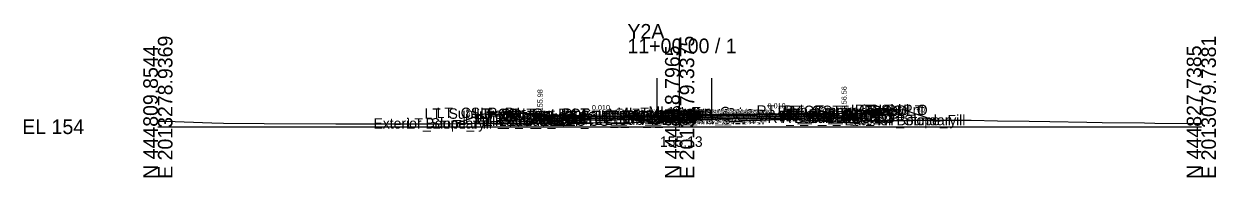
# Model space of a CAD drawing. Extents: x -26 to 203, y -10 to 5517.
# Drawn here: x -25.7 to 202.8, y 1990.3 to 2019.8 of the extents above; entities that cross this region are included whole.
import ezdxf

# ---------------------------------------------------------------- set-up
doc = ezdxf.new("R2010")
doc.units = 0
for name, color, linetype in [('Default', 7, 'Continuous'), ('Exist Cross Section Cell', 7, 'Continuous'), ('Exist XS Center Line Elevation Label', 7, 'Continuous'), ('Exist XS Ground Line', 7, 'Continuous'), ('Prop CMT Conc Surface', 7, 'Continuous'), ('Prop CMT Concrete Structures', 7, 'Continuous'), ('Prop CMT Pvmt Course 1', 7, 'Continuous'), ('Prop CMT Pvmt Course 1 CG', 7, 'Continuous'), ('Prop CMT Pvmt Course 2', 7, 'Continuous'), ('Prop CMT Pvmt Course 3', 7, 'Continuous'), ('Prop CMT Pvmt Surface', 7, 'Continuous'), ('Prop CMT Slope Grass', 7, 'Continuous'), ('Prop CMT Subgrade Earthwork', 7, 'Continuous'), ('Prop XS Earthwork Shape', 7, 'Continuous'), ('Prop XS Hydro Elevations', 7, 'Continuous'), ('Prop XS SE Text', 7, 'Continuous'), ('Prop XS Side Slope Text', 7, 'Continuous'), ('Scratch_Level_0', 7, 'Continuous'), ('Scratch_Level_3', 7, 'Continuous')]:
    doc.layers.add(name, color=color, linetype=linetype)

msp = doc.modelspace()

# ---------------------------------------------------------------- linework, layer by layer
at = {"layer": 'Exist Cross Section Cell'}
for p, q in [((100, 2000), (100, 2016.93)), ((0, 2000), (100, 2000)), ((100, 2000), (200, 2000))]:
    msp.add_line(p, q, dxfattribs=at)
at = {"layer": 'Exist XS Ground Line'}
msp.add_lwpolyline([(0, 2001.09), (1.54, 2001.04), (10.32, 2000.73), (12.58, 2000.71), (20.36, 2000.6), (34.09, 2000.57), (38.11, 2000.57), (39.58, 2000.57), (43.69, 2000.55), (50.48, 2000.59), (54.5, 2000.59), (60.52, 2000.71), (67.74, 2000.66), (70.57, 2000.66), (78.77, 2000.81), (81.06, 2000.81), (90.15, 2000.74), (91.36, 2000.8), (96.96, 2001), (100, 2001.13), (107.18, 2001.43), (109.11, 2001.5), (109.53, 2001), (111.15, 2001.1), (111.78, 2001.12), (121.22, 2001.44), (122.3, 2001.37), (132.6, 2000.73), (134.22, 2000.63), (134.65, 2001.13), (135.26, 2001.12), (139.78, 2001.11), (140.39, 2001.11), (147.97, 2001.28), (155.86, 2001.25), (160.94, 2001.16), (167.02, 2001.05), (170.98, 2001.01), (178.05, 2000.87), (181.02, 2000.8), (189.09, 2000.74), (191.06, 2000.7), (200, 2000.61)], dxfattribs=at)
at = {"layer": 'Prop CMT Conc Surface'}
for points in [[(73.26, 2001.98), (73.26, 2002.48), (72.76, 2002.48)], [(75.26, 2002.08), (73.26, 2001.98)], [(129.54, 2002.62), (131.54, 2002.56)], [(131.54, 2002.56), (131.54, 2003.06), (132.04, 2003.06)]]:
    msp.add_lwpolyline(points, dxfattribs=at)
at = {"layer": 'Prop CMT Concrete Structures'}
for p, q in [((95.69, 2002.45), (95.68, 2002.29)), ((96.44, 2002.7), (95.69, 2002.45)), ((100.98, 2002.9), (96.44, 2002.7)), ((105.41, 2002.81), (100.98, 2002.9)), ((106.16, 2002.56), (105.41, 2002.81)), ((106.17, 2002.39), (106.16, 2002.56))]:
    msp.add_line(p, q, dxfattribs=at)
for points in [[(75.26, 2002.08), (73.26, 2001.98), (73.26, 2002.48), (72.76, 2002.48)], [(72.76, 2002.48), (72.76, 2001.47), (75.26, 2001.5)], [(75.26, 2001.5), (75.26, 2002.08)], [(94.41, 2002.27), (107.45, 2002.4)], [(129.54, 2002.62), (131.54, 2002.56), (131.54, 2003.06), (132.04, 2003.06)], [(132.04, 2003.06), (132.04, 2002.07), (129.54, 2002.04)], [(129.54, 2002.04), (129.54, 2002.62)], [(142.33, 2003.28), (136.65, 2003.17)], [(136.65, 2003.17), (136.65, 2002.83)], [(136.65, 2002.83), (142.33, 2002.95)], [(142.33, 2002.95), (142.33, 2003.28)]]:
    msp.add_lwpolyline(points, dxfattribs=at)
at = {"layer": 'Prop CMT Pvmt Course 1'}
for points in [[(94.41, 2002.27), (75.26, 2002.08)], [(75.26, 2002.08), (75.26, 2001.83)], [(75.26, 2001.83), (94.41, 2002.02)], [(94.41, 2002.27), (107.45, 2002.4)], [(107.45, 2002.15), (94.41, 2002.02)], [(95.68, 2002.04), (95.68, 2002.29)], [(95.68, 2002.04), (95.68, 2002.29)], [(106.17, 2002.14), (106.17, 2002.39)], [(106.17, 2002.39), (106.17, 2002.14)], [(107.45, 2002.4), (129.54, 2002.62)], [(129.54, 2002.37), (107.45, 2002.15)], [(129.54, 2002.62), (129.54, 2002.37)]]:
    msp.add_lwpolyline(points, dxfattribs=at)
for points in [[(95.68, 2002.04), (95.68, 2002.16), (95.68, 2002.16), (95.68, 2002.04)], [(106.17, 2002.14), (106.17, 2002.27), (106.17, 2002.27), (106.17, 2002.14)]]:
    msp.add_lwpolyline(points, close=True, dxfattribs=at)
at = {"layer": 'Prop CMT Pvmt Course 1 CG'}
for points in [[(129.54, 2002.04), (132.54, 2002.07), (132.87, 2001.74)], [(129.54, 2001.71), (129.54, 2002.04)], [(75.26, 2001.5), (72.26, 2001.47), (71.93, 2001.13)], [(71.93, 2001.13), (75.26, 2001.17)], [(75.26, 2001.17), (75.26, 2001.5)], [(132.87, 2001.74), (129.54, 2001.71)]]:
    msp.add_lwpolyline(points, dxfattribs=at)
at = {"layer": 'Prop CMT Pvmt Course 2'}
for points in [[(94.41, 2002.02), (75.26, 2001.83)], [(94.41, 2002.02), (107.45, 2002.15)], [(95.68, 2001.7), (95.68, 2002.04)], [(95.68, 2001.7), (95.68, 2002.04)], [(106.17, 2001.81), (106.17, 2002.14)], [(106.17, 2002.14), (106.17, 2001.81)], [(107.45, 2002.15), (129.54, 2002.37)], [(129.54, 2002.04), (107.45, 2001.82)], [(129.54, 2002.37), (129.54, 2002.04)], [(75.26, 2001.83), (75.26, 2001.5)], [(75.26, 2001.5), (94.41, 2001.69)], [(107.45, 2001.82), (94.41, 2001.69)]]:
    msp.add_lwpolyline(points, dxfattribs=at)
at = {"layer": 'Prop CMT Pvmt Course 3'}
for points in [[(107.45, 2001.82), (129.54, 2002.04)], [(129.54, 2002.04), (129.54, 2001.71)], [(94.41, 2001.69), (75.26, 2001.5)], [(75.26, 2001.5), (75.26, 2001.17)], [(75.26, 2001.17), (94.41, 2001.36)], [(94.41, 2001.69), (107.45, 2001.82)], [(107.45, 2001.49), (94.41, 2001.36)], [(95.68, 2001.37), (95.68, 2001.7)], [(95.68, 2001.37), (95.68, 2001.7)], [(106.17, 2001.47), (106.17, 2001.81)], [(106.17, 2001.81), (106.17, 2001.47)], [(129.54, 2001.71), (107.45, 2001.49)]]:
    msp.add_lwpolyline(points, dxfattribs=at)
at = {"layer": 'Prop CMT Pvmt Surface'}
for points in [[(94.41, 2002.27), (75.26, 2002.08)], [(94.41, 2002.27), (107.45, 2002.4)], [(107.45, 2002.4), (129.54, 2002.62)]]:
    msp.add_lwpolyline(points, dxfattribs=at)
at = {"layer": 'Prop CMT Slope Grass'}
for points in [[(72.76, 2002.48), (63.26, 2002.67), (57.18, 2000.64)], [(132.04, 2003.06), (142.33, 2003.27)], [(142.33, 2003.27), (142.83, 2003.28), (148.85, 2001.27)]]:
    msp.add_lwpolyline(points, dxfattribs=at)
at = {"layer": 'Prop CMT Subgrade Earthwork'}
for points in [[(75.26, 2001.17), (71.93, 2001.13), (70.53, 2002.53)], [(75.26, 2001.17), (71.93, 2001.13), (70.53, 2002.53)], [(129.54, 2001.71), (132.87, 2001.74), (134.23, 2003.11)], [(129.54, 2001.71), (132.87, 2001.74), (134.23, 2003.11)], [(94.41, 2001.36), (75.26, 2001.17)], [(94.41, 2001.36), (107.45, 2001.49)], [(107.45, 2001.49), (129.54, 2001.71)]]:
    msp.add_lwpolyline(points, dxfattribs=at)
at = {"layer": 'Prop XS Earthwork Shape'}
for points in [[(70.53, 2002.53), (63.26, 2002.67), (57.18, 2000.64), (60.52, 2000.71), (67.74, 2000.66), (70.57, 2000.66), (78.77, 2000.81), (81.06, 2000.81), (90.15, 2000.74), (91.36, 2000.8), (96.96, 2001), (100, 2001.13), (107.18, 2001.43), (109.1, 2001.5), (107.45, 2001.49), (94.41, 2001.36), (75.26, 2001.17), (71.93, 2001.13)], [(142.83, 2003.28), (148.85, 2001.27), (147.97, 2001.28), (140.39, 2001.11), (139.78, 2001.11), (135.26, 2001.12), (134.65, 2001.13), (134.22, 2000.63), (132.6, 2000.73), (122.3, 2001.37), (121.22, 2001.44), (111.78, 2001.12), (111.15, 2001.1), (109.53, 2001), (109.11, 2001.5), (129.54, 2001.71), (132.87, 2001.74), (134.23, 2003.11), (136.65, 2003.17), (136.65, 2002.83), (142.33, 2002.95), (142.33, 2003.27)]]:
    msp.add_lwpolyline(points, close=True, dxfattribs=at)
at = {"layer": 'Scratch_Level_3'}
for p, q in [((95.68, 2002.29), (95.68, 2009.3)), ((106.17, 2002.39), (106.17, 2009.3))]:
    msp.add_line(p, q, dxfattribs=at)

# ---------------------------------------------------------------- texts
at = {"layer": 'Default'}
msp.add_text('-', height=0.0001, dxfattribs=at).set_placement((0, 2000))
at = {"layer": 'Exist Cross Section Cell'}
for s, p in [('Y2A', (90, 2016.93)), ('11+00.00 / 1', (90, 2014.13)), ('EL 154', (-26, 1998.6))]:
    msp.add_text(s, height=2.8, dxfattribs=at).set_placement(p)
for s, p in [('E 2013278.9369', (2.8, 1990)), ('E 2013179.3375', (102.8, 1990)), ('E 2013079.7381', (202.8, 1990)), ('N 444809.8544', (0, 1990)), ('N 444818.7965', (100, 1990)), ('N 444827.7385', (200, 1990))]:
    msp.add_text(s, height=2.8, rotation=90, dxfattribs=at).set_placement(p)
at = {"layer": 'Exist XS Center Line Elevation Label'}
msp.add_text('155.13', height=2, dxfattribs=at).set_placement((96.23, 1996.13))
at = {"layer": 'Prop XS Hydro Elevations'}
for s, p in [('155.98', (73.76, 2002.98)), ('156.56', (132.04, 2003.56))]:
    msp.add_text(s, height=1, rotation=90, dxfattribs=at).set_placement(p)
at = {"layer": 'Prop XS SE Text'}
for p in [(116.86, 2003.5), (83.2, 2003.16)]:
    msp.add_text('0.010', height=1, rotation=0.5729, dxfattribs=at).set_placement(p)
at = {"layer": 'Prop XS Side Slope Text'}
for rotation, p in [(18.4349, (59.23, 2002.12)), (341.5668, (145.3, 2003.25))]:
    msp.add_text('3:1', height=1, rotation=rotation, dxfattribs=at).set_placement(p)
at = {"layer": 'Scratch_Level_0'}
for s, p in [('RT_Shld_O', (133.57, 2002.24)), ('CSLP_Pnt', (134.4, 2002.25)), ('LT_Sub_Trench_Out_DLT', (51.1, 2001.53)), ('LT_CSLP_Pnt', (53.43, 2001.67)), ('LT_CG1_Shelf_Out', (58.81, 2000.47)), ('LT_CG_Top_Face', (60.52, 2001.48)), ('LT_CG_Top_BOC', (61.04, 2001.48)), ('LT_CG_Bot_BOC', (61.08, 2000.47)), ('LT_CG_Top_Gut', (61.5, 2000.98)), ('LT_Sub_OEOP', (62.04, 2000.13)), ('LT_Sub_OEOT_CG', (62.63, 2000.17)), ('LT_CG_Bot_IE', (65.18, 2000.5)), ('LT_Sub_OEOT', (65.34, 2000.17)), ('LT_PV2_OEOT', (65.44, 2000.83)), ('LT_PV3_OEOT', (65.44, 2000.5)), ('LT_PV1_OEOT', (66, 2001.08)), ('LT_Sub_OEEOP', (83.63, 2000.36)), ('LT_PV2_OEEOP', (83.72, 2001.02)), ('LT_PV3_OEEOP', (83.72, 2000.69)), ('LT_PV1_OEEOP', (84.29, 2001.15)), ('LT_PV2_IEEOP', (84.37, 2001.02)), ('LT_PV1_IEEOP', (84.93, 2001.15)), ('LT_PV2_PGL1', (85.3, 2001.02)), ('LT_PV3_PGL1', (85.3, 2000.69)), ('LT_PV2_PGL', (85.63, 2001.02)), ('LT_PV4_PGL', (85.63, 2000.36)), ('LT_PV1_PGL', (86.19, 2001.27)), ('MI_Face In', (86.31, 2001.44)), ('MI_Top In', (88.02, 2001.69)), ('MI_Crown', (94.01, 2001.94)), ('RT_Sub_OEEOP', (96.62, 2000.49)), ('RT_PV2_OEEOP', (96.71, 2001.15)), ('RT_PV3_OEEOP', (96.71, 2000.82)), ('RT_PV1_OEEOP', (97.28, 2001.28)), ('RT_PV2_IEEOP', (97.36, 2001.15)), ('MI_Face Out', (97.71, 2001.57)), ('MI_Top Out', (97.92, 2001.82)), ('RT_PV1_IEEOP', (97.93, 2001.28)), ('RT_PV2_PGL1', (98.29, 2001.15)), ('RT_PV3_PGL1', (98.29, 2000.82)), ('RT_PV2_PGL', (98.62, 2001.15)), ('RT_PV4_PGL', (98.62, 2000.49)), ('MI_Bot Out', (98.71, 2001.4)), ('RT_PV1_PGL', (99.19, 2001.4)), ('RT_Sub_Trench_Out_DLT', (114.75, 2002.11)), ('RT_Sub_OEOT_CG', (116.86, 2000.71)), ('RT_CG_Top_Face', (118.75, 2002.06)), ('RT_CG1_Shelf_Out', (119.04, 2001.07)), ('RT_CG_Bot_IE', (119.4, 2001.04)), ('RT_Sub_OEOT', (119.57, 2000.71)), ('RT_PV2_OEOT', (119.66, 2001.37)), ('RT_PV3_OEOT', (119.66, 2001.04)), ('RT_CG_Top_Gut', (119.73, 2001.56)), ('RT_PV1_OEOT', (120.23, 2001.62)), ('RT_CG_Top_BOC', (120.27, 2002.06)), ('RT_CG_Bot_BOC', (120.31, 2001.07)), ('RT_Sub_OEOP', (122.93, 2000.74)), ('Exterior Boundary', (131.64, 2000.27)), ('RT_Slope_Fill', (137.97, 2000.27)), ('Exterior Boundary', (41.32, 1999.64)), ('LT_Slope_Fill', (47.69, 1999.64))]:
    msp.add_text(s, height=2, dxfattribs=at).set_placement(p)

doc.saveas('drawing.dxf')
